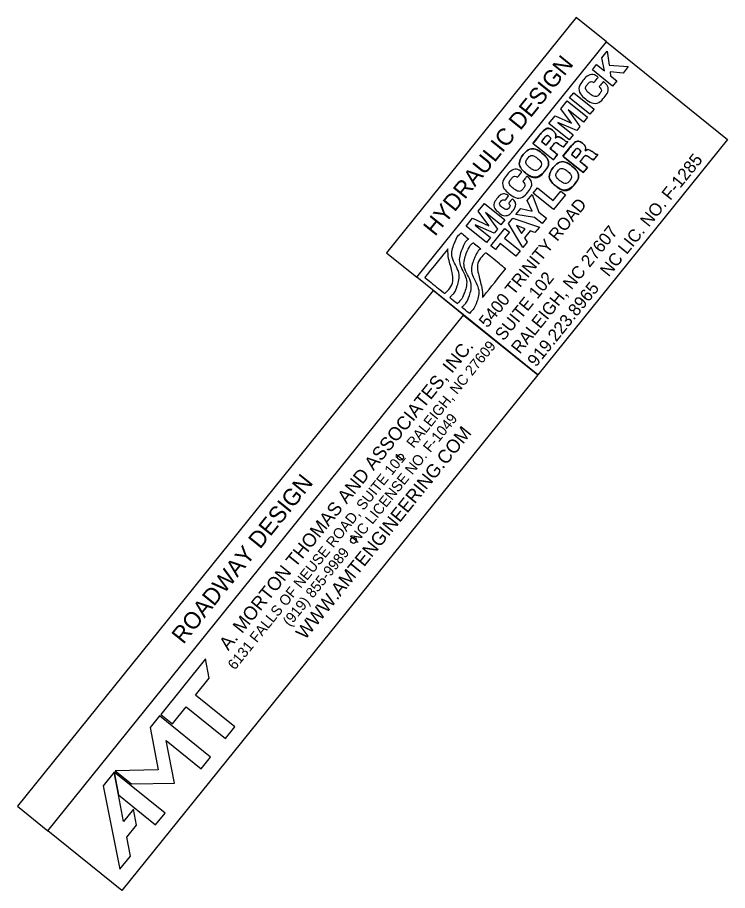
# Model space of a CAD drawing. Extents: x 1487432 to 1489935, y 497862 to 500368.
# Drawn here: x 1489697.4 to 1489935.4, y 499252.8 to 499545.4 of the extents above; entities that cross this region are included whole.
import ezdxf

# ---------------------------------------------------------------- set-up
doc = ezdxf.new("R2010")
doc.units = 0
for name, color, linetype in [('Level 10', 7, 'Continuous'), ('Level 11', 7, 'Continuous'), ('Level 22', 7, 'Continuous')]:
    doc.layers.add(name, color=color, linetype=linetype)

msp = doc.modelspace()

# ---------------------------------------------------------------- linework, layer by layer
at = {"layer": 'Level 10'}
msp.add_lwpolyline([(1489707.56, 499272.82), (1489846.95, 499445.66), (1489871.82, 499425.6), (1489732.44, 499252.76)], close=True, dxfattribs=at)
for points in [[(1489770.28, 499307.66), (1489757.11, 499318.28), (1489761.69, 499323.96), (1489760.41, 499330.39), (1489745.42, 499311.8), (1489749.34, 499308.64), (1489753.95, 499314.36), (1489767.12, 499303.74), (1489770.28, 499307.66)], [(1489750.08, 499288.77), (1489747.28, 499303), (1489758.94, 499293.6), (1489762.1, 499297.52), (1489745.01, 499311.3), (1489741.85, 499307.38), (1489744.53, 499293.24), (1489730.21, 499292.94), (1489735.65, 499288.55), (1489750.08, 499288.77)], [(1489731.24, 499284.81), (1489729.8, 499292.44), (1489726.11, 499287.86), (1489731.76, 499259.89), (1489735.34, 499264.33), (1489734.06, 499270.61), (1489737.34, 499274.67), (1489736.36, 499280.06), (1489732.97, 499275.86), (1489731.24, 499284.81)], [(1489746.89, 499278.66), (1489729.8, 499292.44), (1489731.24, 499284.81), (1489743.73, 499274.74), (1489746.89, 499278.66)]]:
    msp.add_lwpolyline(points, dxfattribs=at)
for centre in [(1489825.83, 499398.01), (1489810.05, 499370.13)]:
    msp.add_circle(centre, 1, dxfattribs=at)
at = {"layer": 'Level 11'}
for p, q in [((1489893.34, 499531.86), (1489895.12, 499534.06)), ((1489895.12, 499534.06), (1489895.77, 499529.39)), ((1489890.11, 499527.86), (1489891.54, 499529.63)), ((1489891.54, 499529.63), (1489894.15, 499527.53)), ((1489894.15, 499527.53), (1489893.34, 499531.86)), ((1489895.77, 499529.39), (1489902.17, 499528.9)), ((1489896.91, 499522.38), (1489890.11, 499527.86)), ((1489900.39, 499526.7), (1489896.06, 499527.17)), ((1489896.06, 499527.17), (1489896.24, 499525.84)), ((1489902.17, 499528.9), (1489900.39, 499526.7)), ((1489896.24, 499525.84), (1489898.34, 499524.15)), ((1489898.34, 499524.15), (1489896.91, 499522.38)), ((1489882.48, 499518.4), (1489883.91, 499520.17)), ((1489889.28, 499512.92), (1489882.48, 499518.4)), ((1489883.91, 499520.17), (1489890.71, 499514.69)), ((1489879.58, 499514.8), (1489881.68, 499517.41)), ((1489883.17, 499509.97), (1489879.58, 499514.8)), ((1489881.68, 499517.41), (1489888.48, 499511.93)), ((1489890.71, 499514.69), (1489889.28, 499512.92)), ((1489875.57, 499509.83), (1489877.68, 499512.44)), ((1489877.68, 499512.44), (1489883.15, 499509.96)), ((1489881.98, 499514.42), (1489881.96, 499514.4)), ((1489881.96, 499514.4), (1489885.97, 499508.81)), ((1489887.14, 499510.26), (1489881.98, 499514.42)), ((1489888.48, 499511.93), (1489887.14, 499510.26)), ((1489882.37, 499504.35), (1489875.57, 499509.83)), ((1489878.57, 499510.19), (1489878.55, 499510.18)), ((1489878.55, 499510.18), (1489883.71, 499506.02)), ((1489884.88, 499507.46), (1489878.57, 499510.19)), ((1489883.15, 499509.96), (1489883.17, 499509.97)), ((1489885.97, 499508.81), (1489884.88, 499507.46)), ((1489883.71, 499506.02), (1489882.37, 499504.35)), ((1489877.69, 499505.05), (1489877.71, 499505.03)), ((1489881.89, 499503.76), (1489880.48, 499502.01)), ((1489887.73, 499500.72), (1489887.75, 499500.7)), ((1489891.94, 499499.43), (1489890.53, 499497.68)), ((1489870.31, 499486.51), (1489871.74, 499488.28)), ((1489871.74, 499488.28), (1489877.01, 499484.03)), ((1489868.31, 499484.04), (1489869.93, 499486.05)), ((1489869.93, 499486.05), (1489872.2, 499480.13)), ((1489877.1, 499481.03), (1489870.31, 499486.51)), ((1489877.01, 499484.03), (1489879.56, 499487.2)), ((1489881.09, 499485.97), (1489877.1, 499481.03)), ((1489879.56, 499487.2), (1489881.09, 499485.97)), ((1489851.88, 499480.44), (1489853.98, 499483.05)), ((1489853.98, 499483.05), (1489860.78, 499477.57)), ((1489869.98, 499480.46), (1489868.31, 499484.04)), ((1489855.46, 499475.62), (1489851.88, 499480.44)), ((1489854.27, 499480.07), (1489854.26, 499480.05)), ((1489854.26, 499480.05), (1489858.27, 499474.46)), ((1489859.43, 499475.91), (1489854.27, 499480.07)), ((1489864.51, 499479.33), (1489866.13, 499481.33)), ((1489866.13, 499481.33), (1489869.98, 499480.46)), ((1489872.2, 499480.13), (1489874.73, 499478.09)), ((1489847.87, 499475.48), (1489849.97, 499478.08)), ((1489849.97, 499478.08), (1489855.45, 499475.6)), ((1489860.78, 499477.57), (1489859.43, 499475.91)), ((1489862.05, 499476.28), (1489863.5, 499478.08)), ((1489863.5, 499478.08), (1489872.35, 499475.14)), ((1489870.77, 499478.36), (1489864.51, 499479.33)), ((1489873.3, 499476.32), (1489870.77, 499478.36)), ((1489874.73, 499478.09), (1489873.3, 499476.32)), ((1489854.67, 499470), (1489847.87, 499475.48)), ((1489850.87, 499475.84), (1489850.85, 499475.82)), ((1489850.85, 499475.82), (1489856.01, 499471.66)), ((1489857.18, 499473.11), (1489850.87, 499475.84)), ((1489855.45, 499475.6), (1489855.46, 499475.62)), ((1489856.07, 499468.86), (1489860.77, 499474.69)), ((1489858.27, 499474.46), (1489857.18, 499473.11)), ((1489860.77, 499474.69), (1489862.29, 499473.46)), ((1489866.8, 499468.26), (1489862.05, 499476.28)), ((1489864.67, 499475.66), (1489864.65, 499475.64)), ((1489864.65, 499475.64), (1489866.41, 499472.95)), ((1489867.65, 499474.49), (1489864.67, 499475.66)), ((1489866.41, 499472.95), (1489867.65, 499474.49)), ((1489869.3, 499473.85), (1489867.39, 499471.48)), ((1489870.86, 499473.29), (1489869.3, 499473.85)), ((1489872.35, 499475.14), (1489870.86, 499473.29)), ((1489856.01, 499471.66), (1489854.67, 499470)), ((1489862.29, 499473.46), (1489860.66, 499471.43)), ((1489860.66, 499471.43), (1489865.93, 499467.18)), ((1489867.39, 499471.48), (1489868.27, 499470.07)), ((1489857.6, 499467.63), (1489856.07, 499468.86)), ((1489859.23, 499469.66), (1489857.6, 499467.63)), ((1489864.5, 499465.41), (1489859.23, 499469.66)), ((1489868.27, 499470.07), (1489866.8, 499468.26)), ((1489865.93, 499467.18), (1489864.5, 499465.41))]:
    msp.add_line(p, q, dxfattribs=at)
for points in [[(1489831.25, 499458.32), (1489894.86, 499537.2), (1489884.71, 499545.39), (1489821.1, 499466.51)], [(1489831.25, 499458.32), (1489894.86, 499537.2), (1489935.43, 499504.48), (1489871.82, 499425.6)], [(1489707.56, 499272.82), (1489846.95, 499445.66), (1489836.79, 499453.85), (1489697.41, 499281.01)], [(1489707.56, 499272.82), (1489846.95, 499445.66), (1489871.82, 499425.6), (1489732.44, 499252.76)]]:
    msp.add_lwpolyline(points, close=True, dxfattribs=at)
for points in [[(1489890.11, 499527.86), (1489891.54, 499529.63), (1489894.15, 499527.53), (1489893.34, 499531.86), (1489895.12, 499534.06), (1489895.77, 499529.39), (1489902.17, 499528.9), (1489900.39, 499526.7), (1489896.06, 499527.17), (1489896.24, 499525.84), (1489898.34, 499524.15), (1489896.91, 499522.38), (1489890.11, 499527.86)], [(1489882.48, 499518.4), (1489883.91, 499520.17), (1489890.71, 499514.69), (1489889.28, 499512.92), (1489882.48, 499518.4)], [(1489875.57, 499509.83), (1489877.68, 499512.44), (1489883.15, 499509.96), (1489883.17, 499509.97), (1489879.58, 499514.8), (1489881.68, 499517.41), (1489888.48, 499511.93), (1489887.14, 499510.26), (1489881.98, 499514.42), (1489881.96, 499514.4), (1489885.97, 499508.81), (1489884.88, 499507.46), (1489878.57, 499510.19), (1489878.55, 499510.18), (1489883.71, 499506.02), (1489882.37, 499504.35), (1489875.57, 499509.83)], [(1489877.05, 499502.81), (1489875.96, 499501.47), (1489878.44, 499499.48), (1489877.01, 499497.71), (1489870.22, 499503.19), (1489873.01, 499506.65)], [(1489874.2, 499505.22), (1489873.06, 499503.81), (1489874.59, 499502.58), (1489875.79, 499504.06)], [(1489887.09, 499498.48), (1489886.01, 499497.14), (1489888.48, 499495.14), (1489887.06, 499493.37), (1489880.26, 499498.85), (1489883.06, 499502.32)], [(1489884.24, 499500.89), (1489883.11, 499499.48), (1489884.64, 499498.25), (1489885.84, 499499.73)], [(1489870.31, 499486.51), (1489871.74, 499488.28), (1489877.01, 499484.03), (1489879.56, 499487.2), (1489881.09, 499485.97), (1489877.1, 499481.03), (1489870.31, 499486.51)], [(1489872.2, 499480.13), (1489874.73, 499478.09), (1489873.3, 499476.32), (1489870.77, 499478.36), (1489864.51, 499479.33), (1489866.13, 499481.33), (1489869.98, 499480.46), (1489868.31, 499484.04), (1489869.93, 499486.05), (1489872.2, 499480.13)], [(1489847.87, 499475.48), (1489849.97, 499478.08), (1489855.45, 499475.6), (1489855.46, 499475.62), (1489851.88, 499480.44), (1489853.98, 499483.05), (1489860.78, 499477.57), (1489859.43, 499475.91), (1489854.27, 499480.07), (1489854.26, 499480.05), (1489858.27, 499474.46), (1489857.18, 499473.11), (1489850.87, 499475.84), (1489850.85, 499475.82), (1489856.01, 499471.66), (1489854.67, 499470), (1489847.87, 499475.48)], [(1489862.05, 499476.28), (1489863.5, 499478.08), (1489872.35, 499475.14), (1489870.86, 499473.29), (1489869.3, 499473.85), (1489867.39, 499471.48), (1489868.27, 499470.07), (1489866.8, 499468.26), (1489862.05, 499476.28)], [(1489862.29, 499473.46), (1489860.66, 499471.43), (1489865.93, 499467.18), (1489864.5, 499465.41), (1489859.23, 499469.66), (1489857.6, 499467.63), (1489856.07, 499468.86), (1489860.77, 499474.69), (1489862.29, 499473.46)], [(1489866.41, 499472.95), (1489867.65, 499474.49), (1489864.67, 499475.66), (1489864.65, 499475.64), (1489866.41, 499472.95)]]:
    msp.add_lwpolyline(points, dxfattribs=at)
for points in [[(1489890.66, 499523.57), (1489889.9, 499524.03), (1489889.11, 499523.78), (1489888.51, 499523.04), (1489887.59, 499521.9), (1489888.24, 499520.65), (1489889.25, 499519.83), (1489890.26, 499519.02), (1489891.62, 499518.65), (1489892.54, 499519.79), (1489893.21, 499520.62), (1489893.12, 499521.47), (1489892.39, 499522.17), (1489892.39, 499522.17), (1489893.82, 499523.94), (1489893.82, 499523.94), (1489895.49, 499522.43), (1489895.48, 499520.32), (1489894.1, 499518.6), (1489892.44, 499516.54), (1489889.79, 499516.48), (1489887.82, 499518.06), (1489885.85, 499519.65), (1489885.36, 499522.25), (1489887.01, 499524.31), (1489888.2, 499525.77), (1489890.41, 499526.61), (1489892.09, 499525.34), (1489892.09, 499525.34), (1489890.66, 499523.57), (1489890.66, 499523.57)], [(1489890.66, 499523.57), (1489889.9, 499524.03), (1489889.11, 499523.78), (1489888.51, 499523.04), (1489887.59, 499521.9), (1489888.24, 499520.65), (1489889.25, 499519.83), (1489890.26, 499519.02), (1489891.62, 499518.65), (1489892.54, 499519.79), (1489893.21, 499520.62), (1489893.12, 499521.47), (1489892.39, 499522.17), (1489892.39, 499522.17), (1489893.82, 499523.94), (1489893.82, 499523.94), (1489895.49, 499522.43), (1489895.48, 499520.32), (1489894.1, 499518.6), (1489892.44, 499516.54), (1489889.79, 499516.48), (1489887.82, 499518.06), (1489885.85, 499519.65), (1489885.36, 499522.25), (1489887.01, 499524.31), (1489888.2, 499525.77), (1489890.41, 499526.61), (1489892.09, 499525.34), (1489892.09, 499525.34), (1489890.66, 499523.57), (1489890.66, 499523.57)], [(1489870.22, 499503.19), (1489870.22, 499503.19), (1489873.01, 499506.65), (1489873.01, 499506.65), (1489873.98, 499507.85), (1489875.47, 499508.59), (1489876.84, 499507.49), (1489877.57, 499506.9), (1489877.99, 499505.98), (1489877.69, 499505.05), (1489877.69, 499505.05), (1489877.71, 499505.03), (1489877.71, 499505.03), (1489878.46, 499505.62), (1489879.44, 499505.17), (1489880.13, 499504.71), (1489880.43, 499504.5), (1489881.45, 499503.72), (1489881.89, 499503.76), (1489881.89, 499503.76), (1489880.48, 499502.01), (1489880.48, 499502.01), (1489880.13, 499502.04), (1489879.44, 499502.55), (1489879.24, 499502.68), (1489878.51, 499503.19), (1489877.71, 499503.64), (1489877.05, 499502.81), (1489877.05, 499502.81), (1489875.96, 499501.47), (1489875.96, 499501.47), (1489875.96, 499501.47), (1489878.44, 499499.48), (1489878.44, 499499.48), (1489878.44, 499499.48), (1489877.01, 499497.71), (1489877.01, 499497.71), (1489877.01, 499497.71), (1489870.22, 499503.19), (1489870.22, 499503.19)], [(1489873.01, 499506.65), (1489873.98, 499507.85), (1489875.47, 499508.59), (1489876.84, 499507.49), (1489877.57, 499506.9), (1489877.99, 499505.98), (1489877.69, 499505.05)], [(1489874.59, 499502.58), (1489874.59, 499502.58), (1489875.79, 499504.06), (1489875.79, 499504.06), (1489876.22, 499504.59), (1489876.17, 499505.11), (1489875.65, 499505.53), (1489875.15, 499505.93), (1489874.6, 499505.72), (1489874.2, 499505.22), (1489874.2, 499505.22), (1489873.06, 499503.81), (1489873.06, 499503.81), (1489873.06, 499503.81), (1489874.59, 499502.58), (1489874.59, 499502.58)], [(1489875.79, 499504.06), (1489876.22, 499504.59), (1489876.17, 499505.11), (1489875.65, 499505.53), (1489875.15, 499505.93), (1489874.6, 499505.72), (1489874.2, 499505.22)], [(1489880.48, 499502.01), (1489880.13, 499502.04), (1489879.44, 499502.55), (1489879.24, 499502.68), (1489878.51, 499503.19), (1489877.71, 499503.64), (1489877.05, 499502.81)], [(1489877.71, 499505.03), (1489878.46, 499505.62), (1489879.44, 499505.17), (1489880.13, 499504.71), (1489880.43, 499504.5), (1489881.45, 499503.72), (1489881.89, 499503.76)], [(1489880.26, 499498.85), (1489880.26, 499498.85), (1489883.06, 499502.32), (1489883.06, 499502.32), (1489884.02, 499503.52), (1489885.52, 499504.26), (1489886.89, 499503.16), (1489887.62, 499502.56), (1489888.03, 499501.65), (1489887.73, 499500.72), (1489887.73, 499500.72), (1489887.75, 499500.7), (1489887.75, 499500.7), (1489888.5, 499501.29), (1489889.48, 499500.84), (1489890.18, 499500.38), (1489890.48, 499500.17), (1489891.5, 499499.39), (1489891.94, 499499.43), (1489891.94, 499499.43), (1489890.53, 499497.68), (1489890.53, 499497.68), (1489890.17, 499497.71), (1489889.49, 499498.22), (1489889.28, 499498.35), (1489888.56, 499498.86), (1489887.76, 499499.31), (1489887.09, 499498.48), (1489887.09, 499498.48), (1489886.01, 499497.14), (1489886.01, 499497.14), (1489886.01, 499497.14), (1489888.48, 499495.14), (1489888.48, 499495.14), (1489888.48, 499495.14), (1489887.06, 499493.37), (1489887.06, 499493.37), (1489887.06, 499493.37), (1489880.26, 499498.85), (1489880.26, 499498.85)], [(1489883.06, 499502.32), (1489884.02, 499503.52), (1489885.52, 499504.26), (1489886.89, 499503.16), (1489887.62, 499502.56), (1489888.03, 499501.65), (1489887.73, 499500.72)], [(1489866.95, 499499.43), (1489868.67, 499501.57), (1489871.22, 499501.51), (1489873.19, 499499.92), (1489875.16, 499498.33), (1489875.76, 499495.86), (1489874.03, 499493.72), (1489872.3, 499491.57), (1489869.76, 499491.63), (1489867.79, 499493.22), (1489865.82, 499494.81), (1489865.22, 499497.28), (1489866.95, 499499.43)], [(1489866.95, 499499.43), (1489868.67, 499501.57), (1489871.22, 499501.51), (1489873.19, 499499.92), (1489875.16, 499498.33), (1489875.76, 499495.86), (1489874.03, 499493.72), (1489873.79, 499493.42), (1489873.54, 499493.17), (1489873.28, 499492.96)], [(1489884.64, 499498.25), (1489884.64, 499498.25), (1489885.84, 499499.73), (1489885.84, 499499.73), (1489886.27, 499500.26), (1489886.21, 499500.78), (1489885.7, 499501.19), (1489885.19, 499501.6), (1489884.64, 499501.39), (1489884.24, 499500.89), (1489884.24, 499500.89), (1489883.11, 499499.48), (1489883.11, 499499.48), (1489883.11, 499499.48), (1489884.64, 499498.25), (1489884.64, 499498.25)], [(1489885.84, 499499.73), (1489886.27, 499500.26), (1489886.21, 499500.78), (1489885.7, 499501.19), (1489885.19, 499501.6), (1489884.64, 499501.39), (1489884.24, 499500.89)], [(1489887.75, 499500.7), (1489888.5, 499501.29), (1489889.48, 499500.84), (1489890.18, 499500.38), (1489890.48, 499500.17), (1489891.5, 499499.39), (1489891.94, 499499.43)], [(1489873.28, 499492.96), (1489871.62, 499491.62), (1489869.49, 499491.85), (1489867.79, 499493.22), (1489865.82, 499494.81), (1489865.22, 499497.28), (1489866.95, 499499.43)], [(1489872.51, 499494.94), (1489873.43, 499496.09), (1489872.77, 499497.34), (1489871.76, 499498.15), (1489870.75, 499498.96), (1489869.39, 499499.34), (1489868.47, 499498.2), (1489867.55, 499497.06), (1489868.21, 499495.8), (1489869.21, 499494.99), (1489870.22, 499494.18), (1489871.59, 499493.8), (1489872.51, 499494.94)], [(1489872.51, 499494.94), (1489873.43, 499496.09), (1489872.77, 499497.34), (1489871.76, 499498.15), (1489870.75, 499498.96), (1489869.39, 499499.34), (1489868.47, 499498.2), (1489867.55, 499497.06), (1489868.21, 499495.8), (1489869.21, 499494.99), (1489870.22, 499494.18), (1489871.59, 499493.8), (1489872.51, 499494.94)], [(1489877, 499495.1), (1489878.73, 499497.24), (1489881.27, 499497.19), (1489883.24, 499495.6), (1489885.21, 499494.01), (1489885.81, 499491.53), (1489884.08, 499489.39), (1489882.35, 499487.25), (1489879.81, 499487.31), (1489877.84, 499488.9), (1489875.87, 499490.49), (1489875.27, 499492.96), (1489877, 499495.1)], [(1489877, 499495.1), (1489878.73, 499497.24), (1489881.27, 499497.19), (1489883.24, 499495.6), (1489885.21, 499494.01), (1489885.81, 499491.53), (1489884.08, 499489.39), (1489883.84, 499489.1), (1489883.59, 499488.85), (1489883.33, 499488.63)], [(1489890.53, 499497.68), (1489890.17, 499497.71), (1489889.49, 499498.22), (1489889.28, 499498.35), (1489888.56, 499498.86), (1489887.76, 499499.31), (1489887.09, 499498.48)], [(1489865.06, 499491.82), (1489864.3, 499492.28), (1489863.5, 499492.04), (1489862.91, 499491.3), (1489861.98, 499490.15), (1489862.64, 499488.9), (1489863.65, 499488.09), (1489864.66, 499487.28), (1489866.02, 499486.9), (1489866.94, 499488.04), (1489867.61, 499488.87), (1489867.52, 499489.73), (1489866.79, 499490.43), (1489866.79, 499490.43), (1489868.22, 499492.2), (1489868.22, 499492.2), (1489869.89, 499490.69), (1489869.88, 499488.58), (1489868.49, 499486.85), (1489866.84, 499484.8), (1489864.19, 499484.73), (1489862.22, 499486.32), (1489860.25, 499487.91), (1489859.76, 499490.51), (1489861.41, 499492.56), (1489862.6, 499494.03), (1489864.81, 499494.87), (1489866.49, 499493.59), (1489866.49, 499493.59), (1489865.06, 499491.82), (1489865.06, 499491.82)], [(1489865.06, 499491.82), (1489864.3, 499492.28), (1489863.5, 499492.04), (1489862.91, 499491.3), (1489861.98, 499490.15), (1489862.64, 499488.9), (1489863.65, 499488.09), (1489864.66, 499487.28), (1489866.02, 499486.9), (1489866.94, 499488.04), (1489867.61, 499488.87), (1489867.52, 499489.73), (1489866.79, 499490.43), (1489866.79, 499490.43), (1489868.22, 499492.2), (1489868.22, 499492.2), (1489869.89, 499490.69), (1489869.88, 499488.58), (1489868.49, 499486.85), (1489866.84, 499484.8), (1489864.19, 499484.73), (1489862.22, 499486.32), (1489860.25, 499487.91), (1489859.76, 499490.51), (1489861.41, 499492.56), (1489862.6, 499494.03), (1489864.81, 499494.87), (1489866.49, 499493.59), (1489866.49, 499493.59), (1489865.06, 499491.82), (1489865.06, 499491.82)], [(1489883.33, 499488.63), (1489881.67, 499487.3), (1489879.54, 499487.53), (1489877.84, 499488.9), (1489875.87, 499490.49), (1489875.27, 499492.96), (1489877, 499495.1)], [(1489882.56, 499490.62), (1489883.48, 499491.76), (1489882.82, 499493.01), (1489881.81, 499493.83), (1489880.81, 499494.64), (1489879.44, 499495.02), (1489878.52, 499493.87), (1489877.6, 499492.73), (1489878.26, 499491.48), (1489879.27, 499490.67), (1489880.28, 499489.85), (1489881.64, 499489.48), (1489882.56, 499490.62)], [(1489882.56, 499490.62), (1489883.48, 499491.76), (1489882.82, 499493.01), (1489881.81, 499493.83), (1489880.81, 499494.64), (1489879.44, 499495.02), (1489878.52, 499493.87), (1489877.6, 499492.73), (1489878.26, 499491.48), (1489879.27, 499490.67), (1489880.28, 499489.85), (1489881.64, 499489.48), (1489882.56, 499490.62)], [(1489860.82, 499484.04), (1489860.39, 499484.36), (1489859.8, 499484.23), (1489859.47, 499483.82), (1489858.74, 499482.92), (1489859.4, 499482.15), (1489860.08, 499481.6), (1489860.72, 499481.09), (1489861.6, 499480.83), (1489862.15, 499481.52), (1489862.6, 499482.08), (1489862.51, 499482.63), (1489862.05, 499483.12), (1489862.05, 499483.12), (1489863.31, 499484.69), (1489863.31, 499484.69), (1489864.52, 499483.49), (1489864.45, 499481.84), (1489863.4, 499480.53), (1489862.2, 499479.05), (1489860.29, 499478.76), (1489858.78, 499479.98), (1489857.21, 499481.25), (1489856.89, 499483.15), (1489858.17, 499484.74), (1489859.16, 499485.97), (1489860.69, 499486.54), (1489862.09, 499485.61), (1489862.09, 499485.61), (1489860.82, 499484.04), (1489860.82, 499484.04)], [(1489860.82, 499484.04), (1489860.39, 499484.36), (1489859.8, 499484.23), (1489859.47, 499483.82), (1489858.74, 499482.92), (1489859.4, 499482.15), (1489860.08, 499481.6), (1489860.72, 499481.09), (1489861.6, 499480.83), (1489862.15, 499481.52), (1489862.6, 499482.08), (1489862.51, 499482.63), (1489862.05, 499483.12), (1489862.05, 499483.12), (1489863.31, 499484.69), (1489863.31, 499484.69), (1489864.52, 499483.49), (1489864.45, 499481.84), (1489863.4, 499480.53), (1489862.2, 499479.05), (1489860.29, 499478.76), (1489858.78, 499479.98), (1489857.21, 499481.25), (1489856.89, 499483.15), (1489858.17, 499484.74), (1489859.16, 499485.97), (1489860.69, 499486.54), (1489862.09, 499485.61), (1489862.09, 499485.61), (1489860.82, 499484.04), (1489860.82, 499484.04)], [(1489844.84, 499449.45), (1489845.54, 499450.32), (1489846.41, 499450.92), (1489847.23, 499452.99), (1489848.77, 499457.78), (1489844.67, 499463.05), (1489846.44, 499467.87), (1489847.48, 499470.32), (1489848.67, 499471.13), (1489848.67, 499471.13), (1489848.67, 499471.13), (1489846.15, 499473.16), (1489846.15, 499473.16), (1489846.15, 499473.16), (1489844.97, 499472.34), (1489843.93, 499469.89), (1489842.15, 499465.08), (1489846.25, 499459.81), (1489844.71, 499455.02), (1489843.89, 499452.95), (1489843.03, 499452.35), (1489842.32, 499451.47), (1489842.32, 499451.47), (1489844.84, 499449.45), (1489844.84, 499449.45)], [(1489844.84, 499449.45), (1489845.54, 499450.32), (1489846.41, 499450.92), (1489847.23, 499452.99), (1489848.77, 499457.78), (1489844.67, 499463.05), (1489846.44, 499467.87), (1489847.48, 499470.32), (1489848.67, 499471.13), (1489848.67, 499471.13), (1489848.67, 499471.13), (1489846.15, 499473.16), (1489846.15, 499473.16), (1489846.15, 499473.16), (1489844.97, 499472.34), (1489843.93, 499469.89), (1489842.15, 499465.08), (1489846.25, 499459.81), (1489844.71, 499455.02), (1489843.89, 499452.95), (1489843.03, 499452.35), (1489842.32, 499451.47), (1489842.32, 499451.47), (1489844.84, 499449.45), (1489844.84, 499449.45)], [(1489841.7, 499467.85), (1489841.6, 499465.49), (1489842.77, 499461.54), (1489843.04, 499460.19), (1489843.7, 499456.84), (1489842.46, 499454.63), (1489840.63, 499452.84), (1489840.63, 499452.84), (1489833.94, 499458.23), (1489833.94, 499458.23), (1489833.94, 499458.23), (1489841.7, 499467.85), (1489841.7, 499467.85)], [(1489841.7, 499467.85), (1489841.6, 499465.49), (1489842.77, 499461.54), (1489843.04, 499460.19), (1489843.7, 499456.84), (1489842.46, 499454.63), (1489840.63, 499452.84), (1489840.63, 499452.84), (1489833.94, 499458.23), (1489833.94, 499458.23), (1489833.94, 499458.23), (1489841.7, 499467.85), (1489841.7, 499467.85)], [(1489848.9, 499446.17), (1489849.61, 499447.04), (1489850.47, 499447.64), (1489851.29, 499449.71), (1489852.83, 499454.51), (1489848.73, 499459.77), (1489850.51, 499464.59), (1489851.55, 499467.04), (1489852.73, 499467.85), (1489852.73, 499467.85), (1489852.73, 499467.85), (1489850.22, 499469.88), (1489850.22, 499469.88), (1489850.22, 499469.88), (1489849.03, 499469.07), (1489847.99, 499466.62), (1489846.22, 499461.8), (1489850.32, 499456.53), (1489848.78, 499451.74), (1489847.96, 499449.67), (1489847.09, 499449.07), (1489846.39, 499448.2), (1489846.39, 499448.2), (1489848.9, 499446.17), (1489848.9, 499446.17)], [(1489848.9, 499446.17), (1489849.61, 499447.04), (1489850.47, 499447.64), (1489851.29, 499449.71), (1489852.83, 499454.51), (1489848.73, 499459.77), (1489850.51, 499464.59), (1489851.55, 499467.04), (1489852.73, 499467.85), (1489852.73, 499467.85), (1489852.73, 499467.85), (1489850.22, 499469.88), (1489850.22, 499469.88), (1489850.22, 499469.88), (1489849.03, 499469.07), (1489847.99, 499466.62), (1489846.22, 499461.8), (1489850.32, 499456.53), (1489848.78, 499451.74), (1489847.96, 499449.67), (1489847.09, 499449.07), (1489846.39, 499448.2), (1489846.39, 499448.2), (1489848.9, 499446.17), (1489848.9, 499446.17)], [(1489853.3, 499451.52), (1489853.4, 499453.88), (1489852.23, 499457.83), (1489851.97, 499459.18), (1489851.31, 499462.52), (1489852.54, 499464.73), (1489854.38, 499466.52), (1489854.38, 499466.52), (1489861.06, 499461.14), (1489861.06, 499461.14), (1489861.06, 499461.14), (1489853.3, 499451.52), (1489853.3, 499451.52)], [(1489853.3, 499451.52), (1489853.4, 499453.88), (1489852.23, 499457.83), (1489851.97, 499459.18), (1489851.31, 499462.52), (1489852.54, 499464.73), (1489854.38, 499466.52), (1489854.38, 499466.52), (1489861.06, 499461.14), (1489861.06, 499461.14), (1489861.06, 499461.14), (1489853.3, 499451.52), (1489853.3, 499451.52)]]:
    msp.add_open_spline(points, degree=3, dxfattribs=at)

# ---------------------------------------------------------------- texts
at = {"layer": 'Level 10'}
for s, height, p in [('A. MORTON THOMAS AND ASSOCIATES, INC.', 4.5, (1489768.09, 499332.92)), ('6131 FALLS OF NEUSE ROAD, SUITE 101   RALEIGH, NC 27609', 3.5, (1489770.29, 499326.48)), ('(919) 855-9989   NC LICENSE NO. F-1049', 3.5, (1489788.76, 499341.02)), ('WWW.AMTENGINEERING.COM', 4.5, (1489793.85, 499336.58))]:
    msp.add_text(s, height=height, rotation=51.1156, dxfattribs=at).set_placement(p)
at = {"layer": 'Level 11'}
for s, height, p in [('919.223.8965   NC LIC. NO. F-1285', 4.1773, (1489871.2, 499428)), ('5400 TRINITY ROAD', 4.1773, (1489854.94, 499441.11)), ('RALEIGH, NC 27607', 4.1773, (1489865.78, 499432.37)), ('SUITE 102', 4.177, (1489860.36, 499436.74))]:
    msp.add_text(s, height=height, rotation=51.1156, dxfattribs=at).set_placement(p)
at = {"layer": 'Level 22'}
for s, p in [('HYDRAULIC DESIGN', (1489837.37, 499471.81)), ('ROADWAY DESIGN', (1489753, 499335.08))]:
    msp.add_text(s, height=5.625, rotation=51.1156, dxfattribs=at).set_placement(p)

doc.saveas('drawing.dxf')
